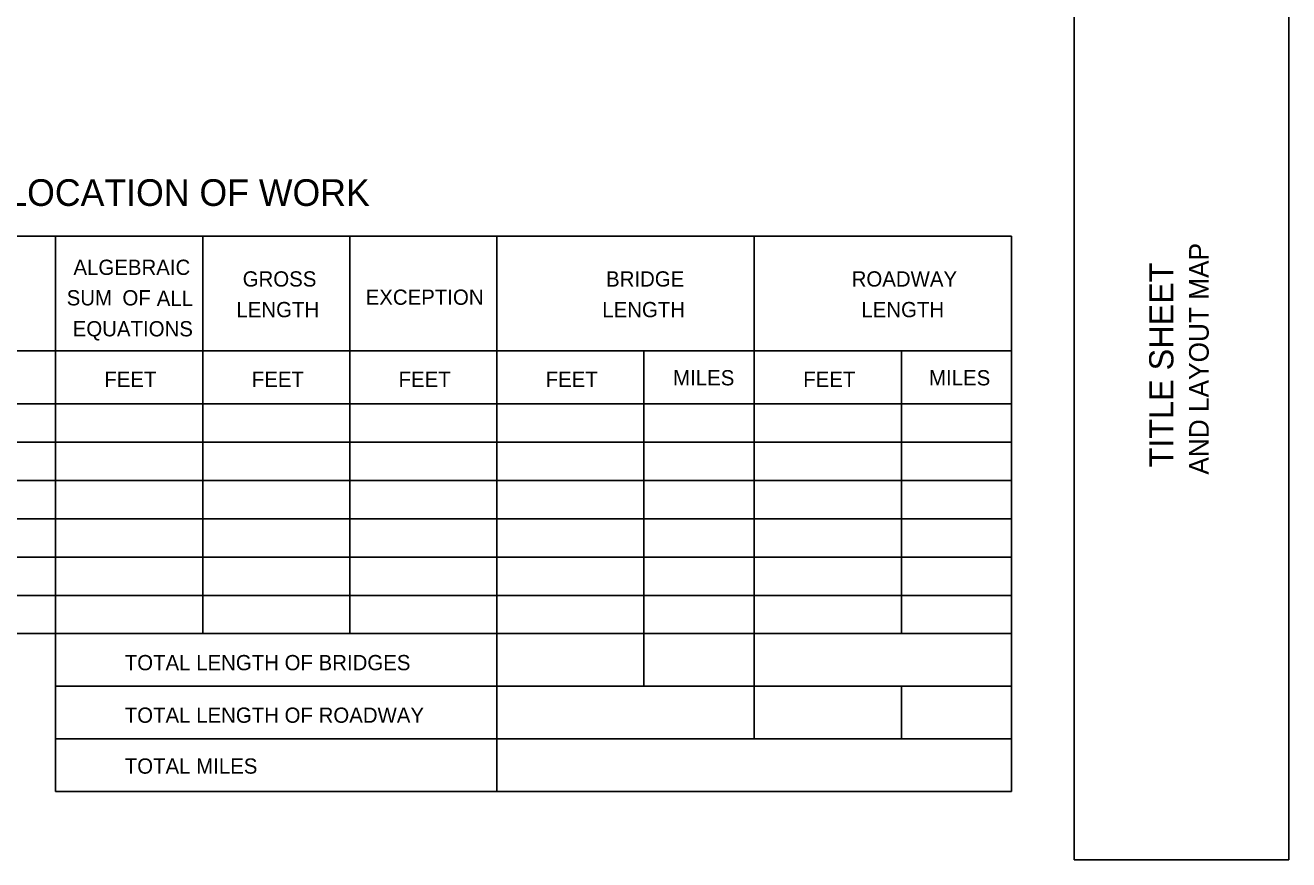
# Model space of a CAD drawing. Extents: x 0.19 to 2.82, y 0.04 to 1.79.
# Drawn here: x 2.129 to 2.817, y 0.042 to 0.496 of the extents above; entities that cross this region are included whole.
import ezdxf

# ---------------------------------------------------------------- set-up
doc = ezdxf.new("R2010")
doc.units = 0
doc.layers.add('Annotation', color=7, linetype='Continuous')
doc.layers.add('Standard Info', color=7, linetype='Continuous')

msp = doc.modelspace()

# ---------------------------------------------------------------- linework, layer by layer
at = {"layer": 'Annotation'}
msp.add_lwpolyline([(2.7, 0.04167), (2.81667, 0.04167), (2.81667, 1.79166), (2.7, 1.79166)], close=True, dxfattribs=at)
at = {"layer": 'Standard Info'}
for p, q in [((1.79596, 0.38087), (2.66596, 0.38087)), ((2.14596, 0.16462), (2.14596, 0.38087)), ((2.22596, 0.16462), (2.22596, 0.38087)), ((2.30596, 0.16462), (2.30596, 0.38087)), ((2.38596, 0.0787), (2.38596, 0.38087)), ((2.52596, 0.10745), (2.52596, 0.38087)), ((2.66596, 0.0787), (2.66596, 0.38087)), ((1.86596, 0.31837), (2.66596, 0.31837)), ((2.46596, 0.13604), (2.46596, 0.31837)), ((2.60596, 0.16462), (2.60596, 0.31837)), ((1.79596, 0.28962), (2.66596, 0.28962)), ((1.79596, 0.26879), (2.66596, 0.26879)), ((1.79596, 0.24795), (2.66596, 0.24795)), ((1.79596, 0.22712), (2.66596, 0.22712)), ((1.79596, 0.20629), (2.66596, 0.20629)), ((1.79596, 0.18545), (2.66596, 0.18545)), ((1.79596, 0.16462), (2.66596, 0.16462)), ((2.14596, 0.16462), (2.14596, 0.0787)), ((2.14596, 0.13604), (2.66596, 0.13604)), ((2.60596, 0.10745), (2.60596, 0.13604)), ((2.14596, 0.10745), (2.66596, 0.10745)), ((2.14596, 0.0787), (2.66596, 0.0787))]:
    msp.add_line(p, q, dxfattribs=at)

# ---------------------------------------------------------------- texts
at = {"layer": 'Annotation'}
for s, height, p in [('             AND LAYOUT MAP              ', 0.0106666, (2.77315, 0.19958)), ('          TITLE SHEET            ', 0.0131666, (2.75394, 0.20606))]:
    msp.add_text(s, height=height, rotation=90, dxfattribs=at).set_placement(p)
at = {"layer": 'Standard Info'}
for s, height, p in [('LENGTH AND LOCATION OF WORK', 0.0145, (1.98932, 0.39726)), ('ALGEBRAIC', 0.0083, (2.15565, 0.35972)), ('GROSS', 0.0083, (2.24771, 0.35339)), ('BRIDGE', 0.0083, (2.44535, 0.35339)), ('ROADWAY', 0.0083, (2.57893, 0.35339)), ('SUM', 0.0083, (2.15197, 0.34314)), ('OF', 0.00833, (2.18229, 0.34312)), ('ALL', 0.00833, (2.20095, 0.34287)), ('EXCEPTION', 0.0083, (2.31458, 0.34347)), ('LENGTH', 0.0083, (2.2443, 0.33672)), ('LENGTH', 0.0083, (2.44328, 0.33672)), ('LENGTH', 0.0083, (2.58422, 0.33672)), ('EQUATIONS', 0.0083, (2.15526, 0.3263)), ('FEET', 0.0083, (2.17245, 0.2988)), ('FEET', 0.0083, (2.25267, 0.2988)), ('FEET', 0.0083, (2.3325, 0.2988)), ('FEET', 0.0083, (2.41251, 0.2988)), ('MILES', 0.0083, (2.48183, 0.29964)), ('FEET', 0.0083, (2.55259, 0.2988)), ('MILES', 0.0083, (2.62102, 0.29964)), ('TOTAL LENGTH OF BRIDGES', 0.0083, (2.18355, 0.14472)), ('TOTAL LENGTH OF ROADWAY', 0.0083, (2.18355, 0.11614)), ('TOTAL MILES', 0.0083, (2.18355, 0.08847))]:
    msp.add_text(s, height=height, dxfattribs=at).set_placement(p)

doc.saveas('drawing.dxf')
